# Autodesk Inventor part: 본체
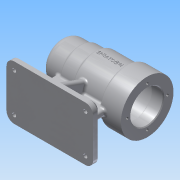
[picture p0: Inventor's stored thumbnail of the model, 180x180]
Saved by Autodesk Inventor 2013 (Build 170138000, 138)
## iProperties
Created: 2016-06
Part Number: 본체
Material: 알루미늄 6061
Document SubType Name: Modeling
Designer: user
Density: 2.71 g/cm^3
Mass: 671.571 g
Surface Area: 648.805 cm^2
Volume: 247.812 cm^3
Author: user
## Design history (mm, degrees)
sketch "스케치1"
  geometry: L1 (46, 35)-(-46, 35); L2 (-56, 25)-(-56, -25); L3 (-46, -35)-(46, -35); L4 (56, -25)-(56, 25); L5 (56, 35)-(-56, -35); L6 (-56, 35)-(56, -35); A1 r 10 centre (46, -25) between (46, -35) and (56, -25); A2 r 10 centre (46, 25) between (56, 25) and (46, 35); A3 r 10 centre (-46, 25) between (-46, 35) and (-56, 25); A4 r 10 centre (-46, -25) between (-56, -25) and (-46, -35); 1 further point
  constraints: 12 end point, 8 point on circle, 8 point on line, 8 tangent, 4 centre point, 3 equal radius, 2 midpoint, 2 parallel, 1 horizontal, 1 perpendicular
  dimensions: "d0" = 112 distance of L5.end L6.end; "d2" = 70 distance of L6.end L5.start; "d3" = 10 radius of A1
extrude "돌출1" new body sketch "스케치1" distance "d4" = 10; taper "d5" = 0 deg
sketch "스케치2"
  geometry: L1 (-56, 25)-(-56, -25) reference; L2 (-46, -35)-(46, -35) reference; L3 (-36, -4)-(36, -4); L4 (36, -4)-(36, 4); L5 (36, 4)-(-36, 4); L6 (-36, 4)-(-36, -4); L7 (-36, -4)-(36, 4); L8 (36, -4)-(-36, 4); 5 further points
  constraints: 12 end point, 6 midpoint, 2 parallel, 1 horizontal, 1 horizontal alignment, 1 perpendicular, 1 vertical alignment
  dimensions: "d10" = 72 distance of L3.start L3.end; "d12" = 8 distance of L5.end L3.start
extrude "돌출2" join sketch "스케치2" distance "d13" = 60; taper "d14" = 0 deg
sketch "스케치3"
  geometry: L1 (10, 28)-(10, -28); L2 (10, 25)-(10, 35) reference; L3 (10, -28)-(70, -6.162); L4 (70, -6.162)-(70, 6.162); L5 (70, 6.162)-(10, 28); L6 (0, -35)-(10, -35) reference; L7 (10, -35)-(10, -25) reference; 1 further point
  constraints: 8 end point, 1 collinear, 1 parallel
  dimensions: "d15" = 7 distance of L2.end L1.start; "d16" = 7 distance from line of L6 L1.end; "d17" = 0 distance between parallel lines of L7 L1; "d18" = 110 deg angle of L7 L3; "d19" = 110 deg angle of L1 L5; "d20" = 60 distance between parallel lines of L1 L4
extrude "돌출3" join sketch "스케치3" stored distance "d21" = 8; taper "d22" = 0 deg
sketch "스케치4"
  geometry: L1 (21, 70)-(29, 70) reference; L2 (29, 70)-(21, 70) reference; C1 r 34 at (25, 70); 1 further point
  constraints: 1 centre point, 1 midpoint
  dimensions: "d23" = 68 diameter of C1
extrude "돌출4" join sketch "스케치4" distance "d24" = 28; taper "d25" = 0 deg
sketch "스케치5"
  geometry: C1 r 30 at (-25, 70); A1 r 34 centre (-25, 70) between (-21, 36.236) and (-29, 36.236) reference; 1 further point
  constraints: 1 centre point, 1 coincident
  dimensions: "d26" = 60 diameter of C1
extrude "돌출5" join sketch "스케치5" distance "d27" = 39; taper "d28" = 0 deg
sketch "스케치6"
  geometry: C1 r 27 at (-25, 70); A1 r 30 centre (-25, 70) between (-21, 40.268) and (-29, 40.268) reference; 1 further point
  constraints: 1 centre point, 1 coincident
  dimensions: "d29" = 54 diameter of C1
extrude "돌출6" join sketch "스케치6" distance "d30" = 20; taper "d31" = 0 deg
sketch "스케치7"
  geometry: C1 r 25 at (-25, 70); A1 r 27 centre (-25, 70) between (-21, 43.298) and (-29, 43.298) reference; 1 further point
  constraints: 1 centre point, 1 coincident
  dimensions: "d32" = 50 diameter of C1
extrude "돌출7" join sketch "스케치7" distance "d33" = 25; taper "d34" = 0 deg
fillet "모깎기1" dims "d35" = 10
sketch "스케치8"
  geometry: C1 r 34 at (0, 0) reference; C2 r 21 at (0, 0); 1 further point
  constraints: 1 centre point, 1 coincident
  dimensions: "d36" = 42 diameter of C2
extrude "돌출8" cut sketch "스케치8" distance "d37" = 15; taper "d38" = 0 deg
sketch "스케치9"
  geometry: C1 r 21 at (0, 0) reference; C2 r 24 at (0, 0); 1 further point
  constraints: 1 centre point, 1 coincident
  dimensions: "d39" = 48 diameter of C2
extrude "돌출9" cut sketch "스케치9" distance "d40" = 54; taper "d41" = 0 deg
sketch "스케치10"
  geometry: C1 r 24 at (0, 0) reference; C2 r 21 at (0, 0); 1 further point
  constraints: 1 centre point, 1 coincident
  dimensions: "d42" = 42 diameter of C2
extrude "돌출10" cut sketch "스케치10" distance "d43" = 12; taper "d44" = 0 deg
sketch "스케치11"
  geometry: C1 r 21 at (0, 0) reference; C2 r 17.5 at (0, 0); 1 further point
  constraints: 1 centre point, 1 coincident
  dimensions: "d45" = 35 diameter of C2
extrude "돌출11" cut sketch "스케치11" distance "d46" = 18; taper "d47" = 0 deg
sketch "스케치12"
  geometry: C1 r 17.5 at (0, 0) reference; C2 r 16 at (0, 0); 1 further point
  constraints: 1 centre point, 1 coincident
  dimensions: "d48" = 32 diameter of C2
extrude "돌출12" cut sketch "스케치12" distance "d49" = 4; taper "d50" = 0 deg
sketch "스케치13"
  geometry: C1 r 16 at (0, 0) reference; C2 r 10.5 at (0, 0); 1 further point
  constraints: 1 centre point, 1 coincident
  dimensions: "d51" = 21 diameter of C2
extrude "돌출13" cut sketch "스케치13" distance "d52" = 3; taper "d53" = 0 deg
sketch "스케치15" dims "d54" = 52
  geometry: C1 r 34 at (0, 0) reference; C2 r 2 at (0, 26); C3 r 2 at (-26, 0); C4 r 2 at (0, -26); C5 r 2 at (26, 0); 2 further points
  constraints: 4 centre point, 1 coincident, 1 vertical alignment, 11 other
  dimensions: "d55" = 4 diameter of C2; "d58" = 360 deg dimension on point (0, 0) C2.centre (derived)
hole "구멍1" sketch "스케치15" at (0, 26), (-26, 0), (0, -26), (26, 0) diameter "d60" = 3.242; stored, may be unused: countersink angle "d64" = 90 deg, drill point angle "d66" = 118 deg; dims "d61" = 8, "d62" = 4, "d63" = 2, "d65" = 11
fillet "모깎기2" dims "d67" = 3, "d68" = 0.3
sketch "스케치16"
  geometry: C1 r 2.5 at (-46, 25); C2 r 2.5 at (-46, -25); C3 r 2.5 at (46, -25); C4 r 2.5 at (46, 25); A1 r 10 centre (-46, -25) between (-56, -25) and (-46, -35) reference; A2 r 10 centre (46, -25) between (46, -35) and (56, -25) reference; A3 r 10 centre (46, 25) between (56, 25) and (46, 35) reference; A4 r 10 centre (-46, 25) between (-46, 35) and (-56, 25) reference; 1 further point
  constraints: 4 centre point, 4 coincident
  dimensions: "d71" = 5 diameter of C1; "d72" = 5 diameter of C2; "d73" = 5 diameter of C3; "d74" = 5 diameter of C4
extrude "돌출14" cut sketch "스케치16" distance "d75" = 6; taper "d76" = 0 deg
sketch "스케치17"
  geometry: C1 r 4.5 at (-46, 25); C2 r 4.5 at (-46, -25); C3 r 4.5 at (46, -25); C4 r 4.5 at (46, 25); A1 r 10 centre (-46, -25) between (-56, -25) and (-46, -35) reference; A2 r 10 centre (46, -25) between (46, -35) and (56, -25) reference; A3 r 10 centre (46, 25) between (56, 25) and (46, 35) reference; A4 r 10 centre (-46, 25) between (-46, 35) and (-56, 25) reference; 1 further point
  constraints: 4 centre point, 4 coincident
  dimensions: "d77" = 9 diameter of C1; "d78" = 9 diameter of C2; "d79" = 9 diameter of C3; "d80" = 9 diameter of C4
extrude "돌출15" cut sketch "스케치17" distance "d81" = 4; taper "d82" = 0 deg
fillet "모깎기4" dims "d84" = 3
node "작업 평면1"
sketch "스케치18"
  geometry: L1 (56, 104)-(56, 36) reference; 3 further points
  constraints: 1 horizontal alignment, 1 midpoint, 1 other
  dimensions: "d87" = 48 distance from line of L1 point (8, 70)
feature "엠보싱1" sketch "스케치18" dims "d0" = 112, "d2" = 70, "d3" = 10, "d10" = 72, "d12" = 8, "d88" = 0.5, "d89" = 0
fillet "모깎기6" dims "d90" = 3
chamfer "모따기1" distance "d91" = 4; stored, may be unused: second distance "d92" = 2, angle "d93" = 45 deg
chamfer "모따기2" distance "d94" = 1; stored, may be unused: second distance "d95" = 2, angle "d96" = 45 deg
node "솔리드1"
